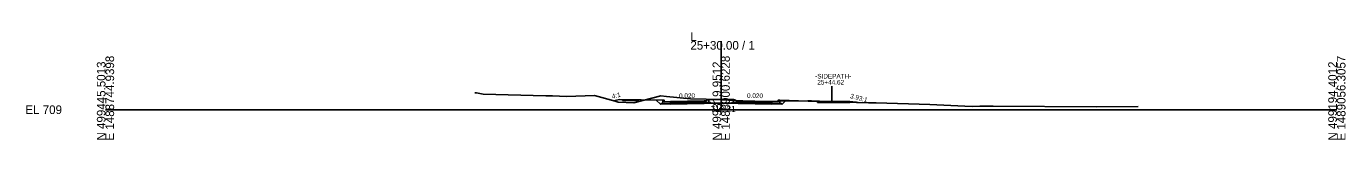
# Model space of a CAD drawing. Extents: x -26 to 4203, y -10 to 9538.
# Drawn here: x 3774.3 to 4202.8, y -9.7 to 25 of the extents above; entities that cross this region are included whole.
import ezdxf

# ---------------------------------------------------------------- set-up
doc = ezdxf.new("R2010")
doc.units = 0
for name, color, linetype in [('Cogo Default Point CELL', 7, 'Continuous'), ('Default', 7, 'Continuous'), ('Exist Horizontal Alignment', 7, 'Continuous'), ('Prop Grid Mask', 7, 'Continuous'), ('Prop Horizontal Alignment', 7, 'Continuous'), ('Prop Horizontal Alignment Curve and Spiral Data', 7, 'Continuous'), ('Prop Horizontal Alignment Station Label', 7, 'Continuous'), ('Prop Horizontal Alignment Tick Label', 7, 'Continuous'), ('Prop Horizontal Alignment Tick Large', 7, 'Continuous'), ('Prop Horizontal Alignment Tick Small', 7, 'Continuous'), ('Scratch_Level_4', 7, 'Continuous'), ('Scratch_Level_5', 7, 'Continuous'), ('Sheet Border Standard 30in CELL', 7, 'Continuous'), ('Sheet Data Field CELL', 7, 'Continuous'), ('Sheet Plot Border Inside CELL', 7, 'Continuous'), ('Sheet Plot Border Outside CELL', 7, 'Continuous')]:
    doc.layers.add(name, color=color, linetype=linetype)

msp = doc.modelspace()

# ---------------------------------------------------------------- linework, layer by layer
at = {"layer": 'Cogo Default Point CELL'}
msp.add_line((4035.99, 7.65), (4035.99, 2.65), dxfattribs=at)
at = {"layer": 'Exist Horizontal Alignment'}
msp.add_lwpolyline([(3920.01, 5.46), (3920.52, 5.42), (3922.71, 5.08), (3943.09, 4.49), (3945.24, 4.52), (3949.76, 4.3), (3958.85, 4.56), (3965.54, 2.73), (3966.59, 2.45), (3971.64, 2.18), (3980.4, 4.49), (3982.19, 4.26), (3989.99, 3.54), (3995.1, 3.45), (4000, 3.21), (4014.05, 2.56), (4018.7, 2.76), (4028.12, 2.86), (4028.47, 2.85), (4028.87, 2.88), (4029.39, 2.85), (4034.5, 2.65), (4041.94, 2.4), (4043.92, 2.34), (4044.42, 2.32), (4047.85, 2.23), (4049, 2.25), (4050.4, 2.26), (4067.81, 1.64), (4079.2, 1.11), (4081.58, 1.07), (4084.07, 1.12), (4088.39, 1.11), (4121.85, 0.93), (4135.49, 1.01)], dxfattribs=at)
at = {"layer": 'Prop Horizontal Alignment Curve and Spiral Data'}
for points in [[(3983.5, 1.85), (3980.24, 1.78), (3978.92, 3.1)], [(3994.5, 2.02), (3983.5, 1.8)], [(3983.5, 1.8), (3983.5, 1.85)], [(3996.76, 2.11), (3994.5, 2.07)], [(3994.5, 2.07), (3994.5, 2.02)], [(3994.5, 2.02), (3994.5, 2.02)], [(3996.76, 2.11), (4003.24, 2.11)], [(4003.24, 2.11), (4005.5, 2.07)], [(4005.5, 2.07), (4005.5, 2.02)], [(4005.5, 2.02), (4005.5, 2.02)], [(4005.5, 2.02), (4016.5, 1.8)], [(4016.5, 1.85), (4019.76, 1.78), (4020.97, 2.99)], [(4016.5, 1.8), (4016.5, 1.85)]]:
    msp.add_lwpolyline(points, dxfattribs=at)
at = {"layer": 'Prop Horizontal Alignment Station Label'}
for points in [[(3981, 3.06), (3967, 3.34), (3965.07, 2.86)], [(3996.01, 3.33), (4003.99, 3.33)], [(4019, 3.06), (4031.28, 2.63), (4031.28, 2.63)], [(4041.76, 2.68), (4043.88, 2.48), (4044.47, 2.33)], [(4041.76, 2.68), (4043.88, 2.48), (4044.51, 2.32)]]:
    msp.add_lwpolyline(points, dxfattribs=at)
at = {"layer": 'Prop Horizontal Alignment Tick Label'}
for points in [[(3994.5, 2.65), (3983.5, 2.43)], [(3983.5, 2.43), (3983.5, 2.18)], [(3983.5, 2.18), (3994.5, 2.4)], [(3994.5, 2.4), (3994.5, 2.65)], [(4005.5, 2.4), (4005.5, 2.65)], [(4005.5, 2.65), (4016.5, 2.43)], [(4016.5, 2.18), (4005.5, 2.4)], [(4016.5, 2.43), (4016.5, 2.18)]]:
    msp.add_lwpolyline(points, dxfattribs=at)
at = {"layer": 'Prop Horizontal Alignment Tick Large'}
for points in [[(3994.5, 2.4), (3983.5, 2.18)], [(3983.5, 2.18), (3983.5, 1.8)], [(3983.5, 1.8), (3994.5, 2.02)], [(3994.5, 2.02), (3994.5, 2.4)], [(4005.5, 2.4), (4016.5, 2.18)], [(4005.5, 2.02), (4005.5, 2.4)], [(4016.5, 1.8), (4005.5, 2.02)], [(4016.5, 2.18), (4016.5, 1.8)]]:
    msp.add_lwpolyline(points, dxfattribs=at)
at = {"layer": 'Prop Horizontal Alignment Tick Small'}
for p, q in [((3968, 2.99), (3968, 3.32)), ((3973, 2.89), (3973, 3.22))]:
    msp.add_line(p, q, dxfattribs=at)
for points in [[(3973, 2.89), (3968, 2.99)], [(3983.5, 2.68), (3981.5, 2.56), (3981.5, 3.06), (3981, 3.06)], [(3981, 3.06), (3981, 2.05), (3983.5, 2.1)], [(3983.5, 2.1), (3983.5, 2.68)], [(3994.5, 2.9), (3995.25, 2.91), (3995.25, 3.08), (3996.01, 3.33)], [(3994.5, 2.32), (3994.5, 2.9)], [(3996.01, 2.35), (3994.5, 2.32)], [(3996.01, 3.33), (3996.01, 2.35)], [(4005.5, 2.9), (4004.75, 2.91), (4004.75, 3.08), (4003.99, 3.33)], [(4003.99, 3.33), (4003.99, 2.35)], [(4003.99, 2.35), (4005.5, 2.32)], [(4005.5, 2.32), (4005.5, 2.9)], [(4016.5, 2.68), (4018.5, 2.56), (4018.5, 3.06), (4019, 3.06)], [(4019, 3.06), (4019, 2.05), (4016.5, 2.1)], [(4016.5, 2.1), (4016.5, 2.68)], [(4041.76, 2.68), (4031.28, 2.63)], [(4031.28, 2.63), (4031.28, 2.3)], [(4031.28, 2.3), (4041.76, 2.34)], [(4041.76, 2.34), (4041.76, 2.68)]]:
    msp.add_lwpolyline(points, dxfattribs=at)
at = {"layer": 'Scratch_Level_4'}
for p, q in [((4000, 0), (4000, 22.25)), ((3800, 0), (4000, 0)), ((4000, 0), (4200, 0))]:
    msp.add_line(p, q, dxfattribs=at)
at = {"layer": 'Sheet Border Standard 30in CELL'}
for points in [[(3994.5, 2.9), (3983.5, 2.68)], [(4005.5, 2.9), (4016.5, 2.68)]]:
    msp.add_lwpolyline(points, dxfattribs=at)
at = {"layer": 'Sheet Data Field CELL'}
for points in [[(3983.5, 2.1), (3980.5, 2.04), (3980.24, 1.78)], [(3980.24, 1.78), (3983.5, 1.85)], [(3983.5, 1.85), (3983.5, 2.1)], [(3994.5, 2.32), (3996.51, 2.36), (3996.76, 2.11)], [(3994.5, 2.07), (3994.5, 2.32)], [(3996.76, 2.11), (3994.5, 2.07)], [(4005.5, 2.32), (4003.49, 2.36), (4003.24, 2.11)], [(4003.24, 2.11), (4005.5, 2.07)], [(4005.5, 2.07), (4005.5, 2.32)], [(4016.5, 2.1), (4019.5, 2.04), (4019.76, 1.78)], [(4016.5, 1.85), (4016.5, 2.1)], [(4019.76, 1.78), (4016.5, 1.85)]]:
    msp.add_lwpolyline(points, dxfattribs=at)
at = {"layer": 'Sheet Plot Border Inside CELL'}
for points in [[(3994.5, 2.9), (3983.5, 2.68)], [(3983.5, 2.68), (3983.5, 2.43)], [(3983.5, 2.43), (3994.5, 2.65)], [(3994.5, 2.65), (3994.5, 2.9)], [(3994.5, 2.65), (3994.5, 2.65), (3994.5, 2.65)], [(4005.5, 2.9), (4016.5, 2.68)], [(4005.5, 2.65), (4005.5, 2.9)], [(4016.5, 2.43), (4005.5, 2.65)], [(4005.5, 2.65), (4005.5, 2.65), (4005.5, 2.65)], [(4016.5, 2.68), (4016.5, 2.43)]]:
    msp.add_lwpolyline(points, dxfattribs=at)
at = {"layer": 'Sheet Plot Border Outside CELL'}
for points in [[(3981.5, 2.56), (3981.5, 3.06), (3981, 3.06)], [(3983.5, 2.68), (3981.5, 2.56)], [(3994.5, 2.9), (3995.25, 2.91), (3995.25, 3.08), (3996.01, 3.33)], [(4005.5, 2.9), (4004.75, 2.91), (4004.75, 3.08), (4003.99, 3.33)], [(4016.5, 2.68), (4018.5, 2.56)], [(4018.5, 2.56), (4018.5, 3.06), (4019, 3.06)], [(4031.28, 2.63), (4041.76, 2.68)]]:
    msp.add_lwpolyline(points, dxfattribs=at)

# ---------------------------------------------------------------- texts
at = {"layer": 'Cogo Default Point CELL'}
for s, p in [('-SIDEPATH-', (4030.53, 10.1)), ('25+44.62', (4031.23, 8.15))]:
    msp.add_text(s, height=1.5, dxfattribs=at).set_placement(p)
at = {"layer": 'Default'}
msp.add_text('-', height=0.0001, dxfattribs=at).set_placement((3800, 0))
msp.add_text('-', height=0.0001, dxfattribs=at).set_placement((3800, 0))
at = {"layer": 'Prop Grid Mask'}
for s, rotation, p in [('4:1', 14.0362, (3964.69, 3.54)), ('3.93:1', 345.737, (4041.76, 3.79))]:
    msp.add_text(s, height=1.5, rotation=rotation, dxfattribs=at).set_placement(p)
at = {"layer": 'Prop Horizontal Alignment'}
msp.add_text('712.21', height=2, dxfattribs=at).set_placement((3996.52, -0.79))
at = {"layer": 'Scratch_Level_4'}
for s, p in [('25+30.00 / 1', (3990, 19.45)), ('L', (3990, 22.25)), ('EL 709', (3774, -1.4))]:
    msp.add_text(s, height=2.8, dxfattribs=at).set_placement(p)
for s, p in [('E 1488744.9398', (3802.8, -10)), ('E 1488900.6228', (4002.8, -10)), ('E 1489056.3057', (4202.8, -10)), ('N 499445.5013', (3800, -10)), ('N 499319.9512', (4000, -10)), ('N 499194.4012', (4200, -10))]:
    msp.add_text(s, height=2.8, rotation=90, dxfattribs=at).set_placement(p)
at = {"layer": 'Scratch_Level_5'}
for rotation, p in [(1.1458, (3986.34, 3.74)), (358.8542, (4008.38, 3.84))]:
    msp.add_text('0.020', height=1.5, rotation=rotation, dxfattribs=at).set_placement(p)

doc.saveas('drawing.dxf')
